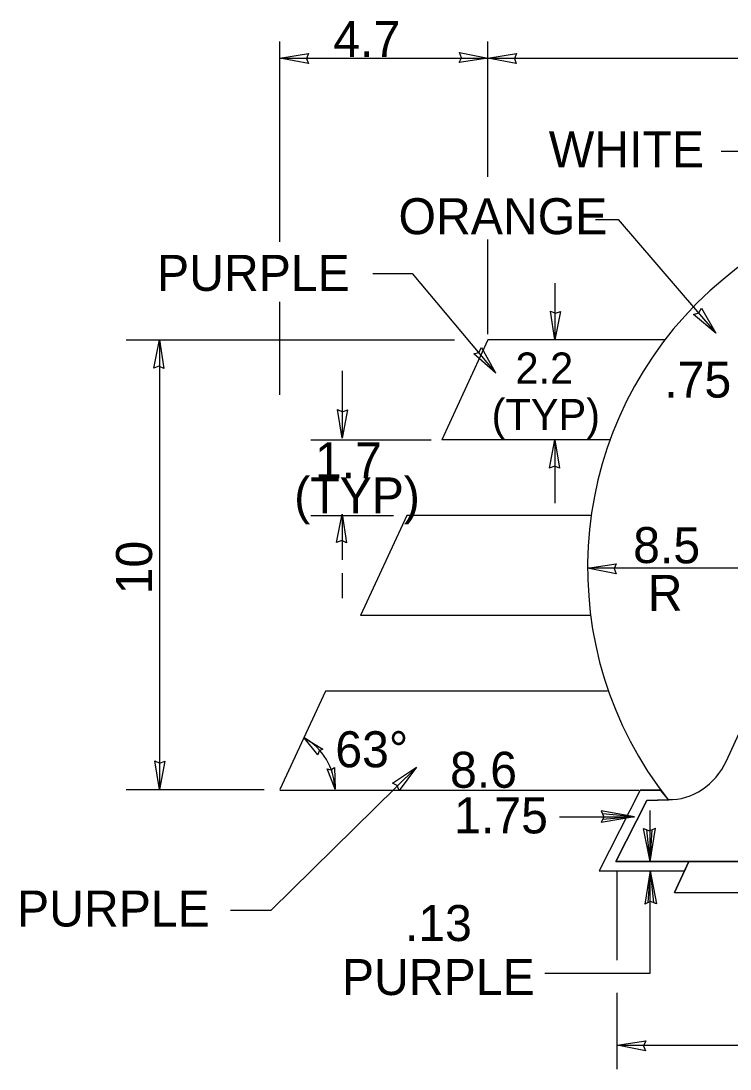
# Model space of a CAD drawing. Extents: x 10268197 to 10269179, y 2141503 to 2142677.
# Drawn here: x 10268462.42 to 10268476.2, y 2142045.42 to 2142065.8 of the extents above; entities that cross this region are included whole.
import ezdxf

# ---------------------------------------------------------------- set-up
doc = ezdxf.new("R2010")
doc.units = 0
for name, color, linetype in [('1', 7, 'Continuous'), ('2', 7, 'Continuous'), ('3', 7, 'Continuous'), ('52', 7, 'Continuous'), ('56', 7, 'Continuous')]:
    doc.layers.add(name, color=color, linetype=linetype)

msp = doc.modelspace()

# ---------------------------------------------------------------- linework, layer by layer
at = {"layer": '1'}
for p, q in [((10268467.453, 2142061.507), (10268467.453, 2142065.401)), ((10268471.492, 2142062.773), (10268471.492, 2142065.401)), ((10268467.453, 2142065.08), (10268471.492, 2142065.08)), ((10268471.492, 2142065.08), (10268513.188, 2142065.08)), ((10268471.492, 2142059.714), (10268471.492, 2142061.549)), ((10268472.796, 2142060.702), (10268472.796, 2142059.602)), ((10268467.453, 2142058.535), (10268467.453, 2142060.34)), ((10268464.462, 2142059.602), (10268470.842, 2142059.602)), ((10268465.11, 2142059.602), (10268465.11, 2142055.216)), ((10268471.492, 2142059.602), (10268470.595, 2142057.66)), ((10268474.933, 2142059.602), (10268471.492, 2142059.602)), ((10268468.659, 2142058.999), (10268468.659, 2142057.688)), ((10268468.053, 2142057.66), (10268470.389, 2142057.66)), ((10268473.868, 2142057.66), (10268470.595, 2142057.66)), ((10268472.796, 2142057.66), (10268472.796, 2142056.426)), ((10268468.053, 2142056.186), (10268469.66, 2142056.186)), ((10268468.659, 2142056.214), (10268468.659, 2142055.323)), ((10268469.915, 2142056.186), (10268469.017, 2142054.244)), ((10268473.501, 2142056.186), (10268469.915, 2142056.186)), ((10268465.11, 2142055.216), (10268465.11, 2142050.857)), ((10268480.718, 2142055.17), (10268473.43, 2142055.159)), ((10268468.659, 2142055.063), (10268468.659, 2142054.576)), ((10268473.49, 2142054.244), (10268469.017, 2142054.244)), ((10268468.337, 2142052.771), (10268467.453, 2142050.857)), ((10268473.817, 2142052.771), (10268468.337, 2142052.771)), ((10268467.284, 2142048.511), (10268470.105, 2142051.293)), ((10268464.462, 2142050.857), (10268467.144, 2142050.857)), ((10268467.453, 2142050.845), (10268474.425, 2142050.845)), ((10268472.881, 2142050.323), (10268474.338, 2142050.323)), ((10268474.643, 2142049.457), (10268474.643, 2142050.447)), ((10268474.643, 2142049.515), (10268474.643, 2142050.149)), ((10268475.399, 2142049.457), (10268475.12, 2142048.853)), ((10268475.34, 2142049.328), (10268475.399, 2142049.457)), ((10268483.237, 2142049.457), (10268475.399, 2142049.457)), ((10268474.003, 2142047.539), (10268474.003, 2142049.267)), ((10268474.643, 2142047.284), (10268474.643, 2142049.277)), ((10268475.12, 2142048.853), (10268483.775, 2142048.853)), ((10268466.491, 2142048.511), (10268467.284, 2142048.511)), ((10268472.601, 2142047.284), (10268474.643, 2142047.284)), ((10268474.003, 2142045.422), (10268474.003, 2142046.905)), ((10268474.003, 2142045.883), (10268483.237, 2142045.883))]:
    msp.add_line(p, q, dxfattribs=at)
for points in [[(10268476.022, 2142063.273), (10268476.5, 2142063.273), (10268479.932, 2142060.051)], [(10268473.582, 2142061.939), (10268474.021, 2142061.939), (10268475.919, 2142059.73)], [(10268469.258, 2142060.891), (10268470.019, 2142060.891), (10268471.642, 2142058.96)]]:
    msp.add_lwpolyline(points, dxfattribs=at)
msp.add_arc((10268467.361, 2142050.848), 1.158, 0.8256, 61.0937, dxfattribs=at)
at = {"layer": '2'}
for p, q in [((10268476.127, 2142051.417), (10268479.601, 2142058.998)), ((10268474.451, 2142050.845), (10268473.654, 2142049.277)), ((10268474.451, 2142050.845), (10268474.855, 2142050.845)), ((10268474.582, 2142050.646), (10268473.977, 2142049.457)), ((10268474.995, 2142050.658), (10268474.582, 2142050.646)), ((10268473.977, 2142049.457), (10268483.237, 2142049.457)), ((10268475.12, 2142048.853), (10268475.399, 2142049.457)), ((10268473.654, 2142049.277), (10268475.316, 2142049.277)), ((10268475.12, 2142048.853), (10268483.775, 2142048.853))]:
    msp.add_line(p, q, dxfattribs=at)
msp.add_arc((10268480.718, 2142055.17), 7.288, 51.9618, 218.2529, dxfattribs=at)
msp.add_ellipse((10268475.018, 2142052.047), major_axis=(0, 1.387), ratio=0.897229, start_param=3.121696, end_param=4.241135, dxfattribs=at)
at = {"layer": '3'}
msp.add_lwpolyline([(10268474.843, 2142050.845), (10268474.451, 2142050.845), (10268473.654, 2142049.277), (10268475.316, 2142049.277), (10268475.399, 2142049.457), (10268473.977, 2142049.457), (10268474.582, 2142050.646), (10268475.006, 2142050.658), (10268474.987, 2142050.678)], close=True, dxfattribs=at)
at = {"layer": '52'}
for p, q in [((10268473.743, 2142050.328), (10268473.692, 2142050.215)), ((10268474.338, 2142050.323), (10268473.692, 2142050.215)), ((10268474.338, 2142050.323), (10268473.694, 2142050.442)), ((10268473.694, 2142050.442), (10268473.743, 2142050.328)), ((10268474.338, 2142050.323), (10268473.719, 2142050.383)), ((10268474.338, 2142050.323), (10268473.719, 2142050.275)), ((10268474.643, 2142049.457), (10268474.518, 2142050.099)), ((10268474.518, 2142050.099), (10268474.633, 2142050.052)), ((10268474.643, 2142049.457), (10268474.579, 2142050.074)), ((10268474.633, 2142050.052), (10268474.746, 2142050.103)), ((10268474.643, 2142049.457), (10268474.746, 2142050.103)), ((10268474.643, 2142049.457), (10268474.686, 2142050.076)), ((10268474.643, 2142049.277), (10268474.54, 2142048.63)), ((10268474.643, 2142049.277), (10268474.6, 2142048.658)), ((10268474.643, 2142049.277), (10268474.768, 2142048.634)), ((10268474.643, 2142049.277), (10268474.708, 2142048.658)), ((10268474.653, 2142048.682), (10268474.54, 2142048.63)), ((10268474.768, 2142048.634), (10268474.653, 2142048.682))]:
    msp.add_line(p, q, dxfattribs=at)
for points in [[(10268467.453, 2142065.08), (10268468.01, 2142065.167), (10268467.968, 2142065.072), (10268468.006, 2142064.973)], [(10268471.492, 2142065.08), (10268470.936, 2142064.992), (10268470.978, 2142065.087), (10268470.94, 2142065.187)], [(10268471.492, 2142065.08), (10268472.049, 2142065.167), (10268472.007, 2142065.072), (10268472.045, 2142064.973)], [(10268472.796, 2142059.602), (10268472.708, 2142060.159), (10268472.803, 2142060.117), (10268472.902, 2142060.155)], [(10268475.919, 2142059.73), (10268475.49, 2142060.095), (10268475.59, 2142060.125), (10268475.64, 2142060.219)], [(10268465.11, 2142059.602), (10268465.198, 2142059.046), (10268465.102, 2142059.088), (10268465.003, 2142059.05)], [(10268471.642, 2142058.96), (10268471.217, 2142059.33), (10268471.317, 2142059.358), (10268471.368, 2142059.452)], [(10268468.659, 2142057.688), (10268468.571, 2142058.244), (10268468.667, 2142058.202), (10268468.766, 2142058.24)], [(10268472.796, 2142057.66), (10268472.883, 2142057.104), (10268472.788, 2142057.146), (10268472.689, 2142057.108)], [(10268468.659, 2142056.214), (10268468.747, 2142055.657), (10268468.652, 2142055.699), (10268468.552, 2142055.661)], [(10268473.43, 2142055.159), (10268473.986, 2142055.247), (10268473.944, 2142055.152), (10268473.983, 2142055.053)], [(10268467.92, 2142051.862), (10268468.283, 2142051.643), (10268468.212, 2142051.609), (10268468.186, 2142051.534)], [(10268465.11, 2142050.857), (10268465.022, 2142051.414), (10268465.117, 2142051.372), (10268465.217, 2142051.41)], [(10268468.522, 2142050.866), (10268468.368, 2142051.259), (10268468.444, 2142051.243), (10268468.511, 2142051.287)], [(10268470.105, 2142051.293), (10268469.77, 2142050.84), (10268469.733, 2142050.937), (10268469.637, 2142050.981)], [(10268474.003, 2142045.883), (10268474.559, 2142045.971), (10268474.518, 2142045.876), (10268474.556, 2142045.777)]]:
    msp.add_lwpolyline(points, close=True, dxfattribs=at)
at = {"layer": '56'}
msp.add_lwpolyline([(10268471.636, 2142058.962), (10268471.642, 2142058.96), (10268471.636, 2142058.965), (10268471.638, 2142058.964), (10268471.638, 2142058.964), (10268471.638, 2142058.964), (10268471.64, 2142058.962), (10268471.638, 2142058.963), (10268471.64, 2142058.962), (10268471.636, 2142058.963), (10268471.638, 2142058.962), (10268471.636, 2142058.962), (10268471.636, 2142058.962), (10268471.638, 2142058.963), (10268471.636, 2142058.965)], dxfattribs=at)
msp.add_lwpolyline([(10268471.636, 2142058.962), (10268471.642, 2142058.96), (10268471.636, 2142058.965), (10268471.638, 2142058.964), (10268471.638, 2142058.964), (10268471.638, 2142058.964), (10268471.64, 2142058.962), (10268471.638, 2142058.963), (10268471.64, 2142058.962), (10268471.636, 2142058.963), (10268471.638, 2142058.962), (10268471.636, 2142058.962), (10268471.636, 2142058.962), (10268471.638, 2142058.963), (10268471.636, 2142058.965)], dxfattribs=at)
msp.add_lwpolyline([(10268471.636, 2142058.962), (10268471.642, 2142058.96), (10268471.636, 2142058.965), (10268471.638, 2142058.964), (10268471.638, 2142058.964), (10268471.638, 2142058.964), (10268471.64, 2142058.962), (10268471.638, 2142058.963), (10268471.64, 2142058.962), (10268471.636, 2142058.963), (10268471.638, 2142058.962), (10268471.636, 2142058.962), (10268471.636, 2142058.962), (10268471.638, 2142058.963), (10268471.636, 2142058.965)], dxfattribs=at)

# ---------------------------------------------------------------- texts
at = {"layer": '1'}
for s, height, p in [('4.7', 0.7, (10268468.489, 2142065.102)), ('WHITE', 0.7, (10268472.676, 2142062.954)), ('ORANGE', 0.7, (10268469.756, 2142061.655)), ('PURPLE', 0.7, (10268465.064, 2142060.553)), ('2.2', 0.6037, (10268472.028, 2142058.751)), ('.75', 0.7, (10268474.919, 2142058.478)), ('(TYP)', 0.6037, (10268471.564, 2142057.847)), ('1.7', 0.7, (10268468.132, 2142056.909)), ('(TYP)', 0.7, (10268467.728, 2142056.226)), ('63°', 0.7, (10268468.528, 2142051.29)), ('8.6', 0.7, (10268470.757, 2142050.891)), ('1.75', 0.7, (10268470.837, 2142050.004)), ('PURPLE', 0.7, (10268462.344, 2142048.193)), ('.13', 0.7, (10268469.88, 2142047.911)), ('PURPLE', 0.7, (10268468.657, 2142046.861))]:
    msp.add_text(s, height=height, dxfattribs=at).set_placement(p)
for s, rotation, p in [('8.5', 359.5763, (10268474.313, 2142055.263)), ('10', 90, (10268464.968, 2142054.652)), ('R', 0.3852, (10268474.601, 2142054.328))]:
    msp.add_text(s, height=0.7, rotation=rotation, dxfattribs=at).set_placement(p)

doc.saveas('drawing.dxf')
